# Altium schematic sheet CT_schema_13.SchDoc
size 742 x 377 mm
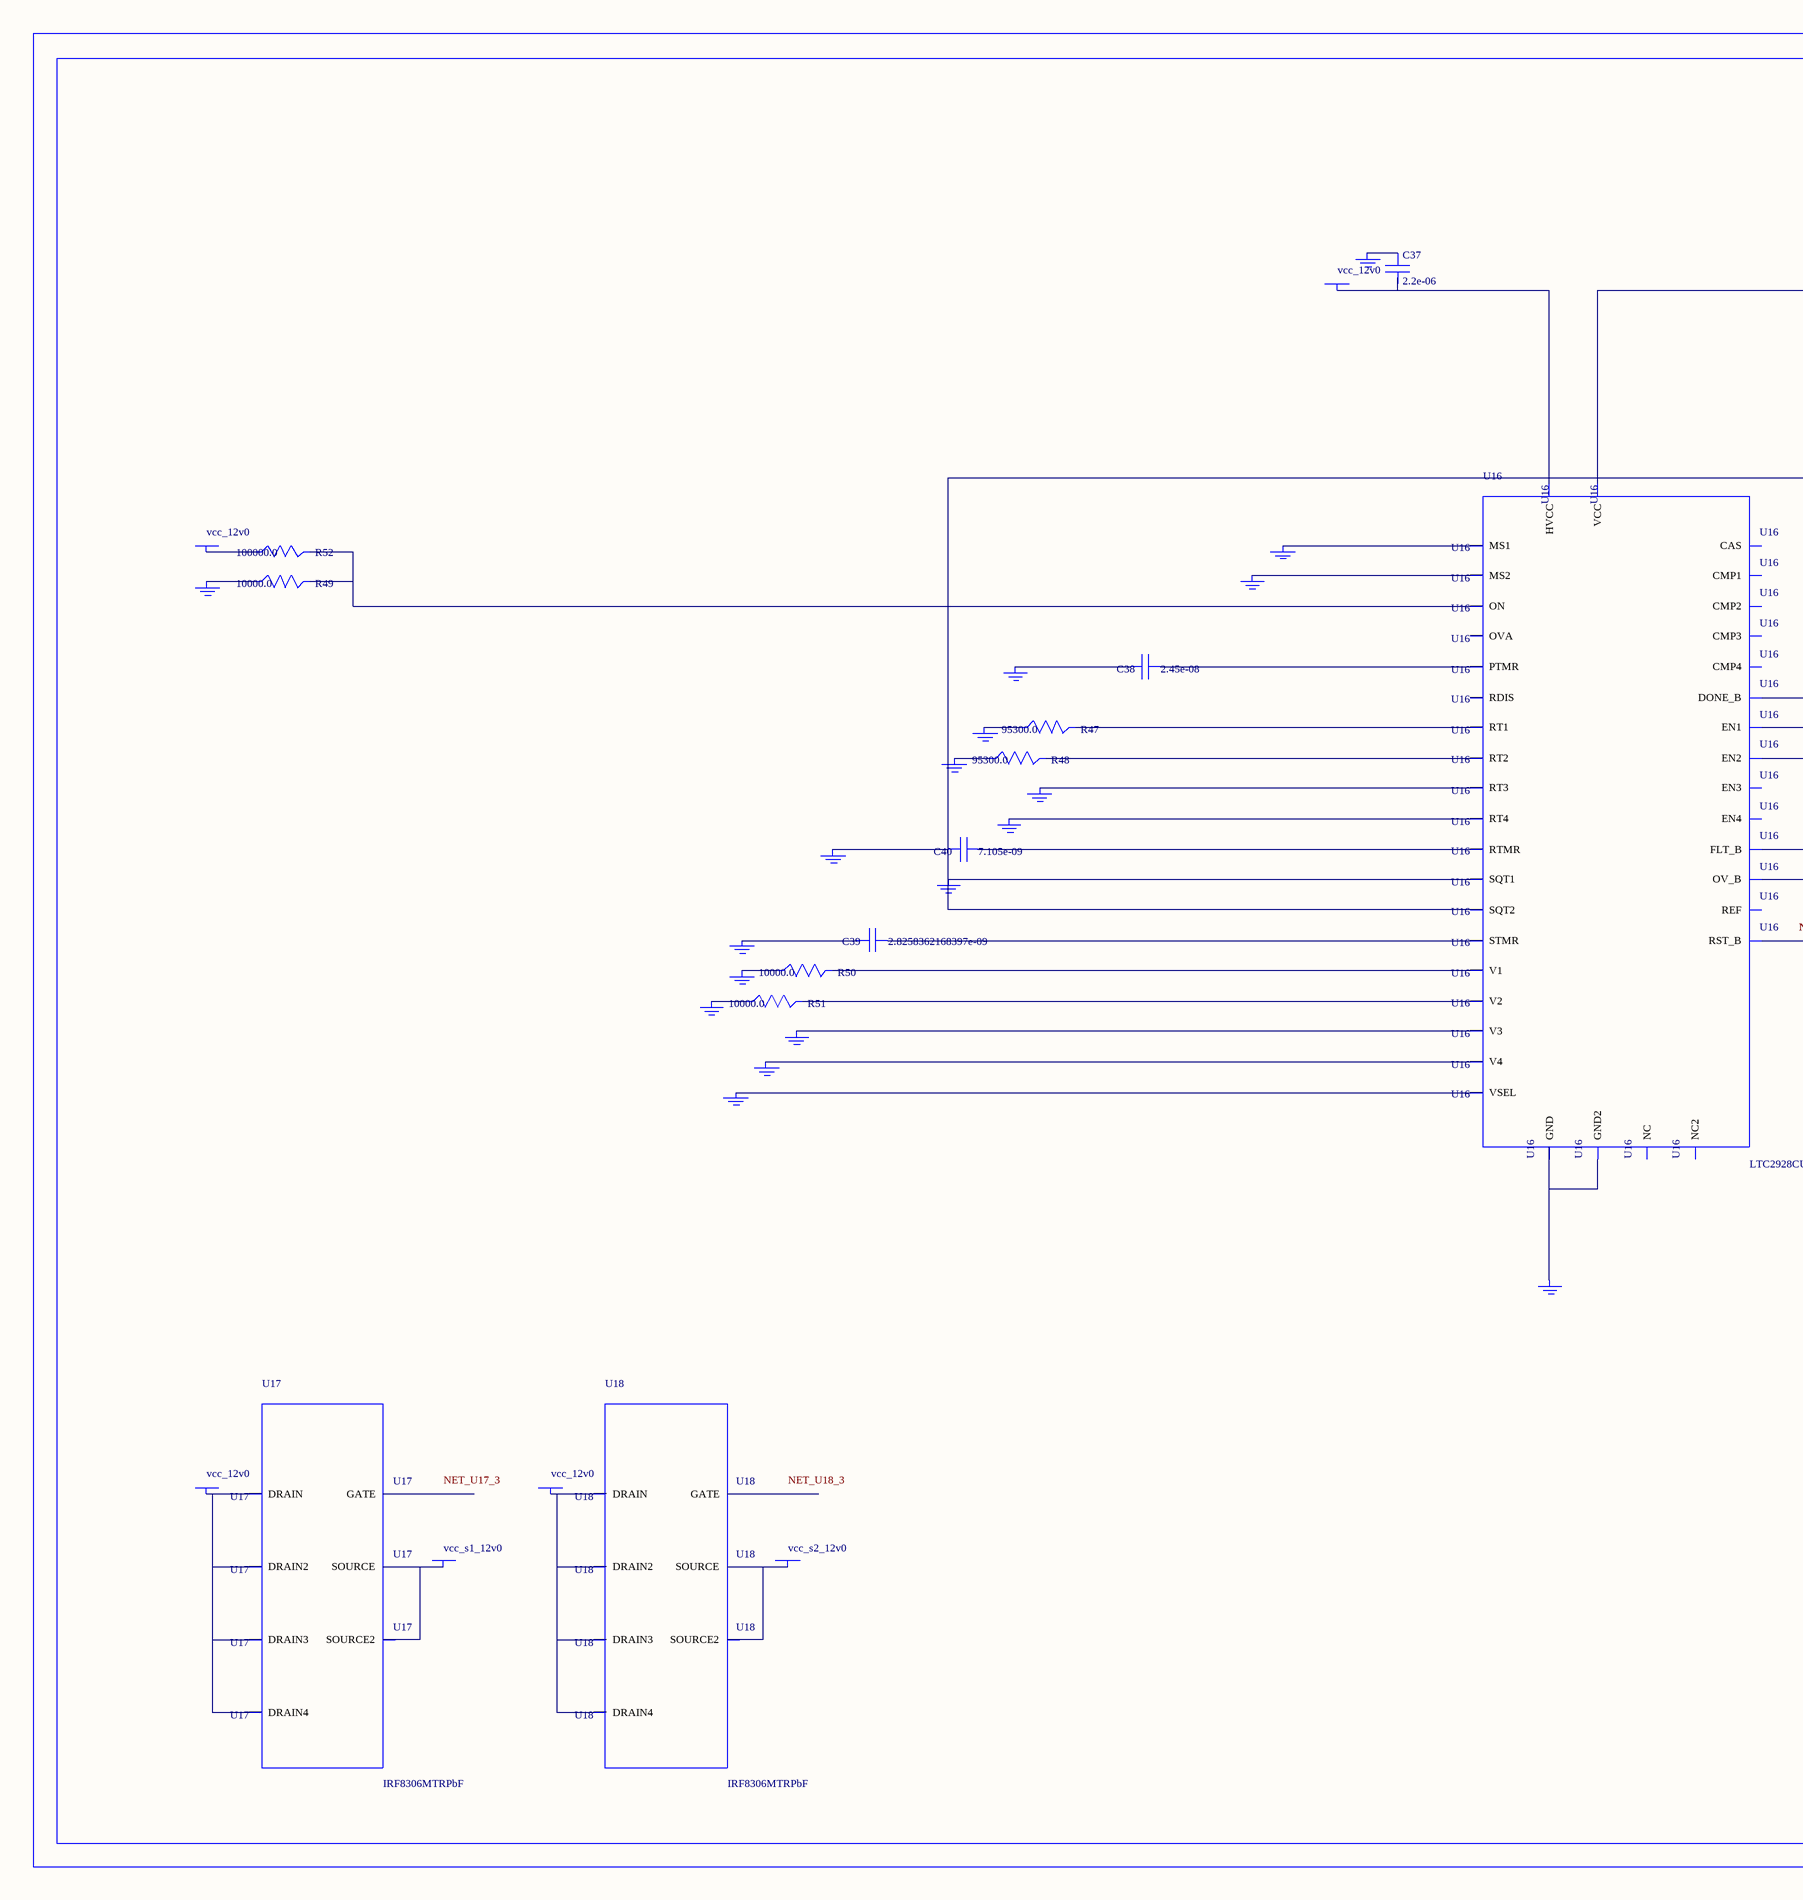
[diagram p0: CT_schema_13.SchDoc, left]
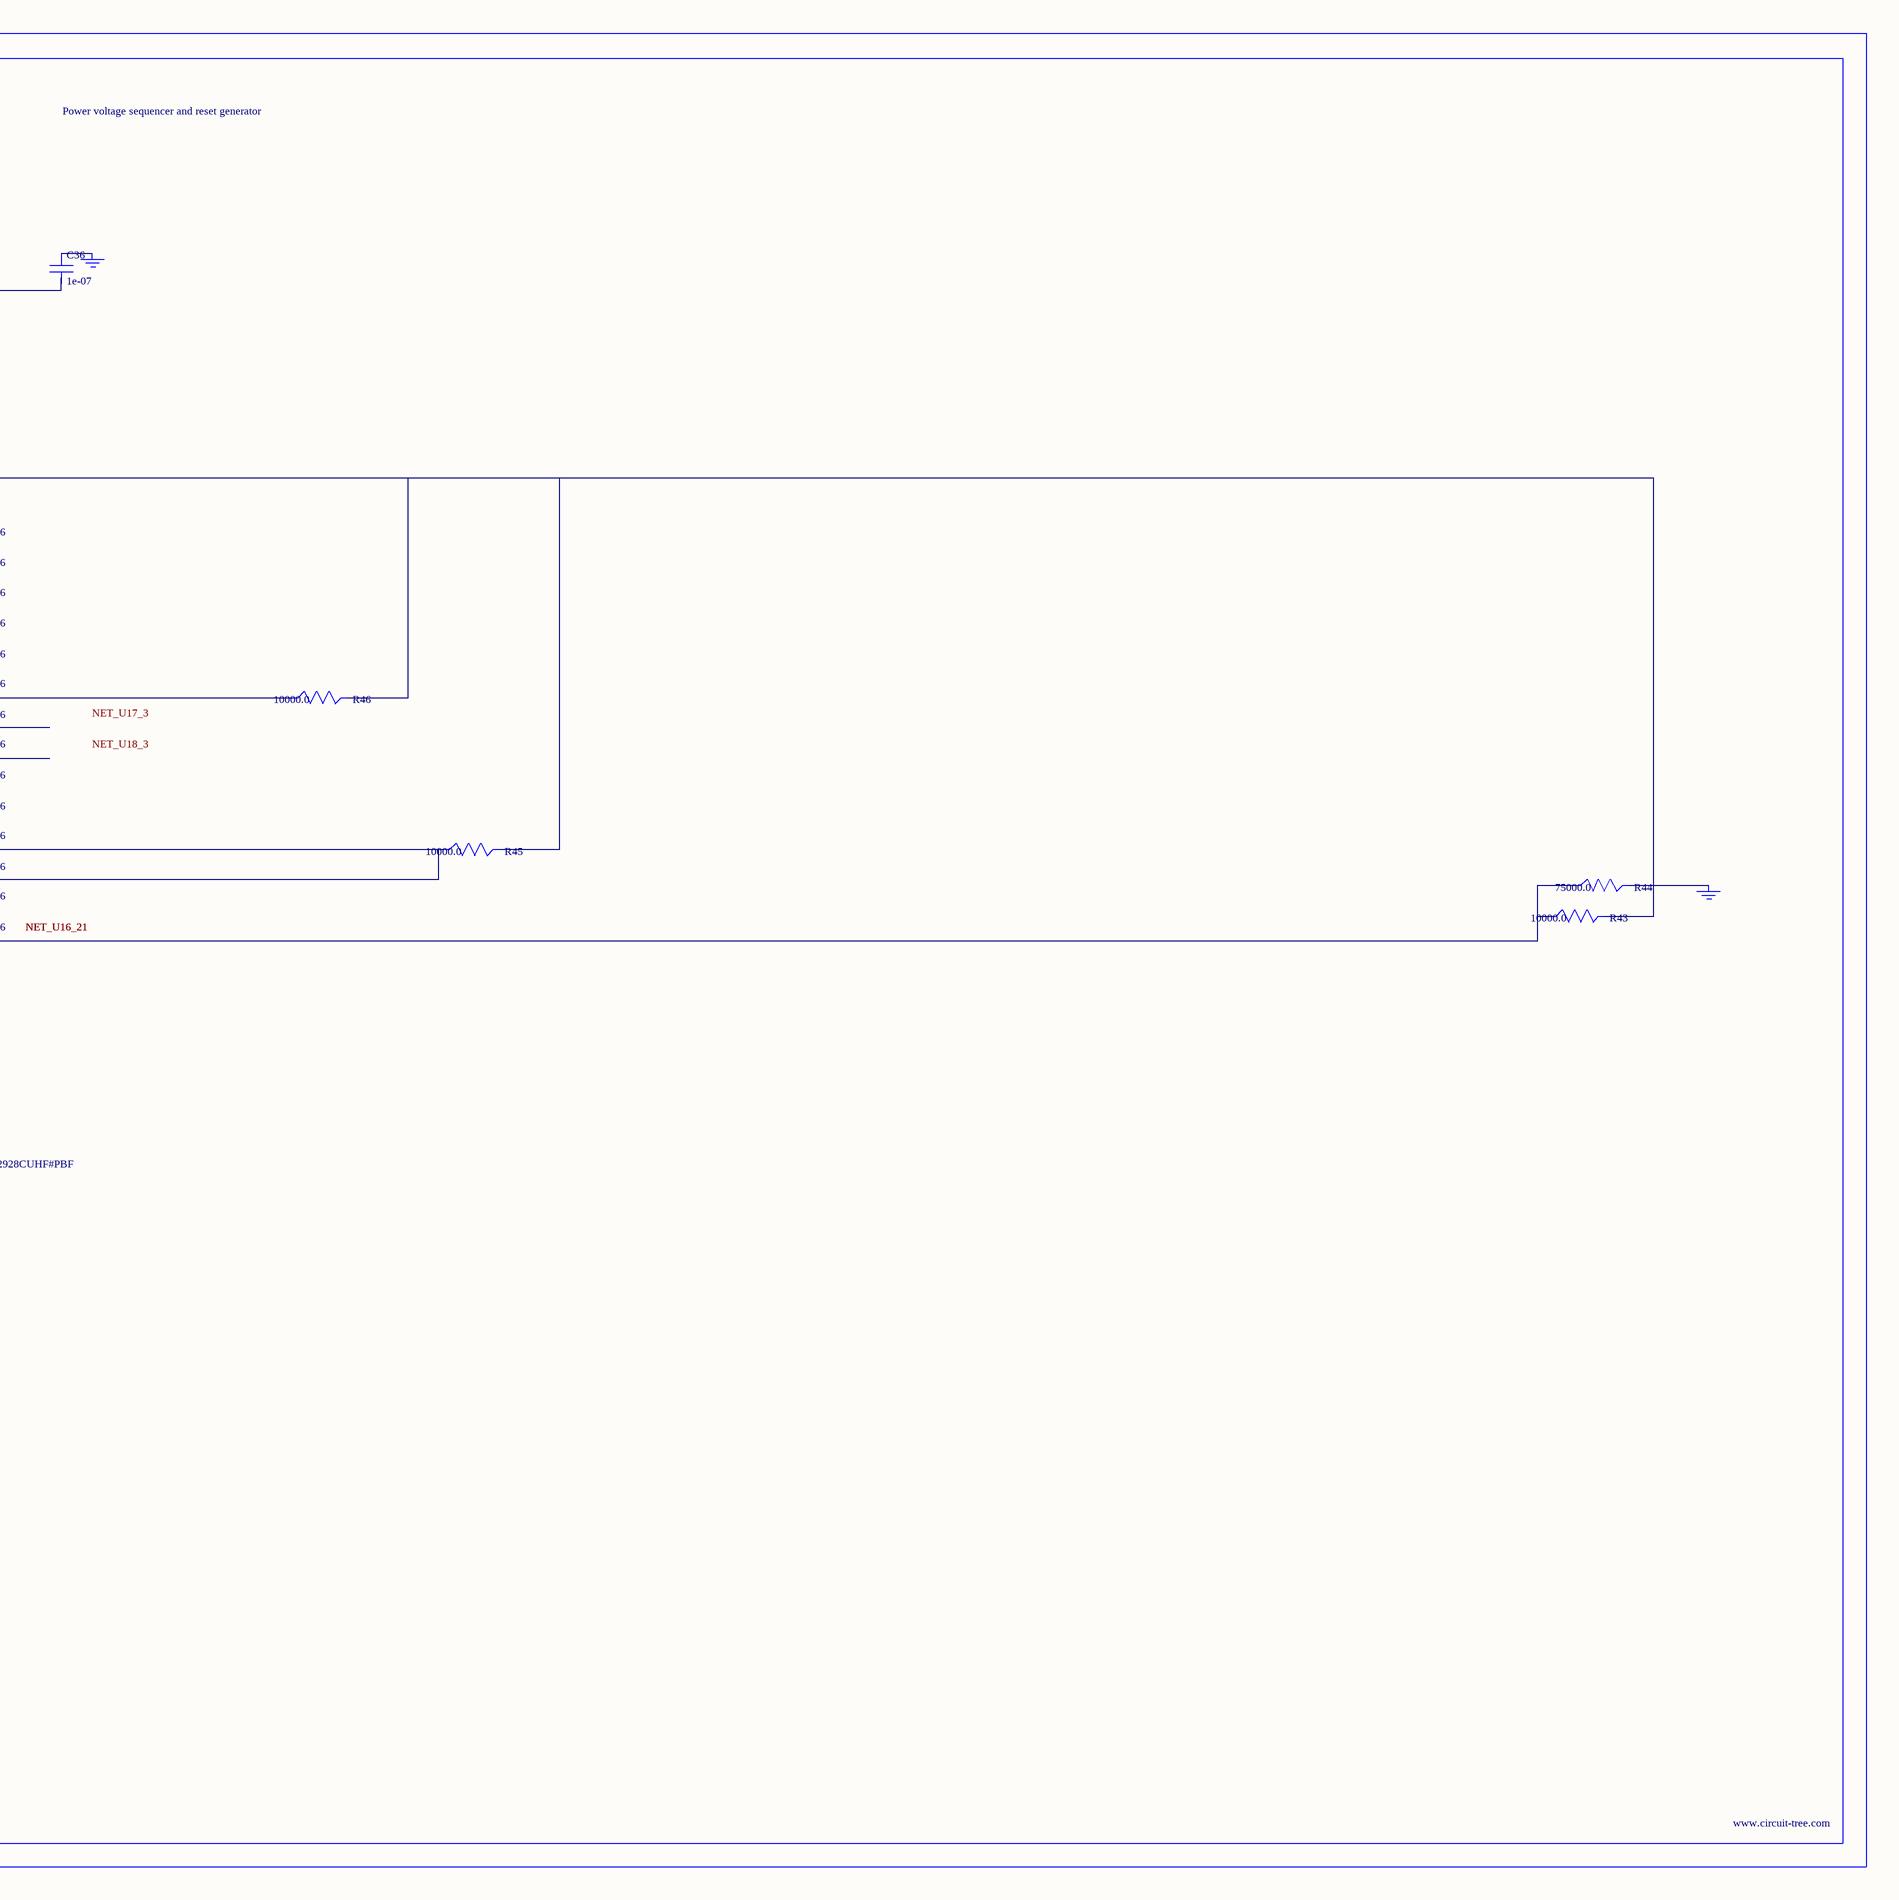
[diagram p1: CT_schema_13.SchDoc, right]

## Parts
BORDER12  (no value)
C36  1e-07  [C0402]
C37  2.2e-06  [C0603]
C38  2.45e-08  [R0603]
C39  2.8258362168397e-09  [R0603]
C40  7.105e-09  [R0603]
GND_INSTANCE_12_0  (no value)
GND_INSTANCE_12_1  (no value)
GND_INSTANCE_12_2  (no value)
GND_INSTANCE_12_3  (no value)
GND_INSTANCE_12_4  (no value)
GND_INSTANCE_12_5  (no value)
GND_INSTANCE_12_6  (no value)
GND_INSTANCE_12_7  (no value)
GND_INSTANCE_12_8  (no value)
GND_INSTANCE_12_9  (no value)
GND_INSTANCE_12_10  (no value)
GND_INSTANCE_12_11  (no value)
GND_INSTANCE_12_12  (no value)
GND_INSTANCE_12_13  (no value)
GND_INSTANCE_12_14  (no value)
GND_INSTANCE_12_15  (no value)
GND_INSTANCE_12_16  (no value)
GND_INSTANCE_12_17  (no value)
GND_INSTANCE_12_18  (no value)
GND_INSTANCE_12_19  (no value)
POWER_INSTANCE_12_0  vcc_12v0
POWER_INSTANCE_12_1  vcc_12v0
POWER_INSTANCE_12_2  vcc_12v0
POWER_INSTANCE_12_3  vcc_s1_12v0
POWER_INSTANCE_12_4  vcc_12v0
POWER_INSTANCE_12_5  vcc_s2_12v0
R43  10000.0  [R0603]
R44  75000.0  [R0603]
R45  10000.0  [R0603]
R46  10000.0  [R0603]
R47  95300.0  [R0603]
R48  95300.0  [R0603]
R49  10000.0  [R0603]
R50  10000.0  [R0603]
R51  10000.0  [R0603]
R52  100000.0  [R0603]
U16  LTC2928CUHF#PBF  [QFN-38_UHF]
U17  IRF8306MTRPbF  [IRF8306MTRPBF]
U18  IRF8306MTRPbF  [IRF8306MTRPBF]

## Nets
NetC36_1: C36.1 GND_INSTANCE_12_10.0(GND)
NetC36_2: C36.2 C40.2 GND_INSTANCE_12_5.0(GND) GND_INSTANCE_12_15.0(GND) R43.2 R45.2 R46.2 U16.10(SQT1) U16.11(SQT2) U16.22(VCC)
NetC37_1: C37.1 GND_INSTANCE_12_11.0(GND)
NetC37_2: C37.2 POWER_INSTANCE_12_1.0(PWR) U16.23(HVCC)
NetC38_1: C38.1 U16.27(PTMR)
NetC38_2: C38.2 GND_INSTANCE_12_14.0(GND)
NetC39_1: C39.1 U16.26(STMR)
NetC39_2: C39.2 GND_INSTANCE_12_13.0(GND)
NetC40_1: C40.1 U16.28(RTMR)
NetGND_INSTANCE_12_0_0: GND_INSTANCE_12_0.0(GND) R50.1
NetGND_INSTANCE_12_1_0: GND_INSTANCE_12_1.0(GND) R47.1
NetGND_INSTANCE_12_2_0: GND_INSTANCE_12_2.0(GND) R48.1
NetGND_INSTANCE_12_3_0: GND_INSTANCE_12_3.0(GND) U16.8(RT3)
NetGND_INSTANCE_12_4_0: GND_INSTANCE_12_4.0(GND) U16.9(RT4)
NetGND_INSTANCE_12_6_0: GND_INSTANCE_12_6.0(GND) U16.12(MS1)
NetGND_INSTANCE_12_7_0: GND_INSTANCE_12_7.0(GND) U16.13(MS2)
NetGND_INSTANCE_12_8_0: GND_INSTANCE_12_8.0(GND) R49.1
NetGND_INSTANCE_12_9_0: GND_INSTANCE_12_9.0(GND) R44.2
NetGND_INSTANCE_12_12_0: GND_INSTANCE_12_12.0(GND) U16.25(VSEL)
NetGND_INSTANCE_12_16_0: GND_INSTANCE_12_16.0(GND) U16.30(V4)
NetGND_INSTANCE_12_17_0: GND_INSTANCE_12_17.0(GND) U16.32(V3)
NetGND_INSTANCE_12_18_0: GND_INSTANCE_12_18.0(GND) R51.1
NetGND_INSTANCE_12_19_0: GND_INSTANCE_12_19.0(GND) U16.24(GND) U16.39(GND2)
NetPOWER_INSTANCE_12_0_0: POWER_INSTANCE_12_0.0(PWR) R52.1
NetPOWER_INSTANCE_12_2_0: POWER_INSTANCE_12_2.0(PWR) U17.1(DRAIN) U17.2(DRAIN2) U17.6(DRAIN3) U17.7(DRAIN4)
NetPOWER_INSTANCE_12_3_0: POWER_INSTANCE_12_3.0(PWR) U17.4(SOURCE) U17.5(SOURCE2)
NetPOWER_INSTANCE_12_4_0: POWER_INSTANCE_12_4.0(PWR) U18.1(DRAIN) U18.2(DRAIN2) U18.6(DRAIN3) U18.7(DRAIN4)
NetPOWER_INSTANCE_12_5_0: POWER_INSTANCE_12_5.0(PWR) U18.4(SOURCE) U18.5(SOURCE2)
NetR43_1: R43.1 R44.1 U16.21(RST_B)
NetR45_1: R45.1 U16.19(FLT_B) U16.20(OV_B)
NetR46_1: R46.1 U16.18(DONE_B)
NetR47_2: R47.2 U16.6(RT1)
NetR48_2: R48.2 U16.7(RT2)
NetR49_2: R49.2 R52.2 U16.16(ON)
NetR50_2: R50.2 U16.3(V1)
NetR51_2: R51.2 U16.38(V2)

Not connected (* = marked no-connect by the designer): U16 1(OVA) 2(EN1) 4(NC) 5(REF) 14(RDIS) 15(CAS) 17(NC2) 29(EN4) 31(EN3) 33(CMP3) 34(CMP4) 35(CMP1) 36(CMP2) 37(EN2); U17 3(GATE); U18 3(GATE)

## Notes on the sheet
- Labels drawn without touching a wire or pin: NET_U17_3, NET_U18_3

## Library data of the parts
BORDER12 = BORDER_PAGE12
C36 = C0402C104K3RACTU
C37 = GRM188R61H225KE1115D
C38 = C38
C39 = C39
C40 = C40
GND_INSTANCE_12_0-GND_INSTANCE_12_19 = GND
POWER_INSTANCE_12_0-POWER_INSTANCE_12_5 = PWR
R43 R45 R46 R49-R51 = RC0603JR-0710KL
R44 = RC0603JR-0775KL
R47 R48 = RC0603FR-0795K3L
R52 = RC0603JR-07100KL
